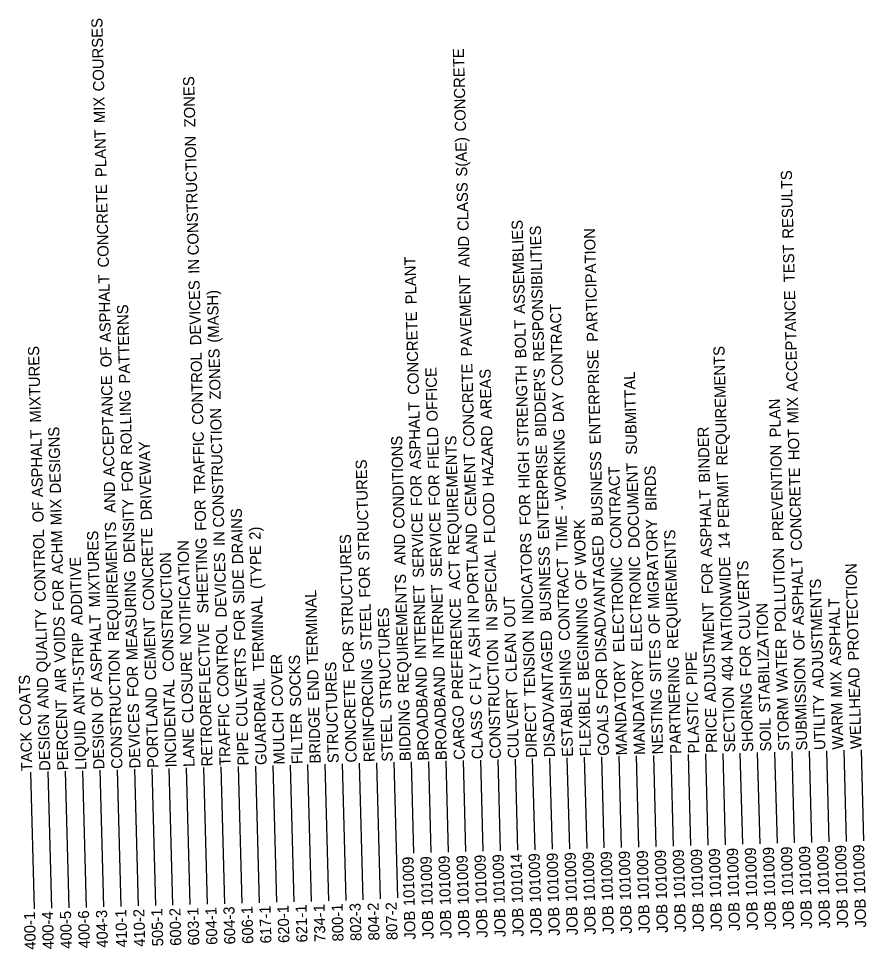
# Model space of a CAD drawing. Extents: x 1930579 to 1931706, y 595585 to 597808.
# Drawn here: x 1931091 to 1931550, y 596431 to 596935 of the extents above; entities that cross this region are included whole.
import ezdxf

# ---------------------------------------------------------------- set-up
doc = ezdxf.new("R2010")
doc.units = 0
doc.layers.add('Default', color=7, linetype='Continuous')

msp = doc.modelspace()

# ---------------------------------------------------------------- linework, layer by layer
at = {"layer": 'Default'}
for p, q in [((1931389.43, 596485.8), (1931388.11, 596535.11)), ((1931398.79, 596486.05), (1931397.46, 596535.36)), ((1931408.14, 596486.3), (1931406.82, 596535.61)), ((1931417.5, 596486.55), (1931416.18, 596535.86)), ((1931426.86, 596486.8), (1931425.53, 596536.11)), ((1931436.21, 596487.06), (1931434.89, 596536.37)), ((1931445.57, 596487.31), (1931444.25, 596536.62)), ((1931454.93, 596487.56), (1931453.6, 596536.87)), ((1931464.28, 596487.81), (1931462.96, 596537.12)), ((1931473.64, 596488.06), (1931472.32, 596537.37)), ((1931483, 596488.31), (1931481.67, 596537.62)), ((1931492.35, 596488.56), (1931491.03, 596537.87)), ((1931501.71, 596488.81), (1931500.39, 596538.12)), ((1931511.07, 596489.07), (1931509.74, 596538.37)), ((1931520.42, 596489.32), (1931519.1, 596538.63)), ((1931529.78, 596489.57), (1931528.46, 596538.88)), ((1931539.14, 596489.82), (1931537.81, 596539.13)), ((1931548.49, 596490.07), (1931547.17, 596539.38)), ((1931202.96, 596456.16), (1931200.97, 596530.09)), ((1931212.32, 596456.42), (1931210.33, 596530.34)), ((1931221.67, 596456.67), (1931219.69, 596530.59)), ((1931231.03, 596456.92), (1931229.04, 596530.84)), ((1931240.39, 596457.17), (1931238.4, 596531.09)), ((1931249.74, 596457.42), (1931247.76, 596531.34)), ((1931259.1, 596457.67), (1931257.11, 596531.59)), ((1931268.46, 596457.92), (1931266.47, 596531.84)), ((1931277.81, 596458.17), (1931275.83, 596532.1)), ((1931287.16, 596458.75), (1931285.18, 596532.35)), ((1931296.51, 596459.37), (1931294.54, 596532.6)), ((1931305.22, 596483.54), (1931303.9, 596532.85)), ((1931314.58, 596483.79), (1931313.25, 596533.1)), ((1931323.93, 596484.04), (1931322.61, 596533.35)), ((1931333.29, 596484.29), (1931331.97, 596533.6)), ((1931342.65, 596484.54), (1931341.32, 596533.85)), ((1931352, 596484.8), (1931350.68, 596534.1)), ((1931361.36, 596485.05), (1931360.04, 596534.36)), ((1931370.72, 596485.3), (1931369.39, 596534.61)), ((1931380.07, 596485.55), (1931378.75, 596534.86)), ((1931100.04, 596453.4), (1931098.05, 596527.32)), ((1931109.39, 596453.65), (1931107.41, 596527.57)), ((1931118.75, 596453.9), (1931116.76, 596527.83)), ((1931128.11, 596454.15), (1931126.12, 596528.08)), ((1931137.46, 596454.41), (1931135.48, 596528.33)), ((1931146.82, 596454.66), (1931144.83, 596528.58)), ((1931156.18, 596454.91), (1931154.19, 596528.83)), ((1931165.53, 596455.16), (1931163.55, 596529.08)), ((1931174.89, 596455.41), (1931172.9, 596529.33)), ((1931184.25, 596455.66), (1931182.26, 596529.58)), ((1931193.6, 596455.91), (1931191.62, 596529.83))]:
    msp.add_line(p, q, dxfattribs=at)

# ---------------------------------------------------------------- texts
for s, p in [(' COURSES', (1931137.81, 596893.29)), (' CONCRETE', (1931333.46, 596871.55)), (' ZONES', (1931187.1, 596873.81)), (' MIX', (1931138.27, 596876.12)), (' PLANT', (1931139.05, 596846.95)), (' CONSTRUCTION', (1931188.96, 596804.65)), (' S(AE)', (1931334.12, 596847.17)), (' RESULTS', (1931510.58, 596813.62)), (' CONCRETE', (1931140.37, 596798.04)), (' CLASS', (1931334.91, 596817.8)), (' ASSEMBLIES', (1931365.37, 596772.94)), (' RESPONSIBILITIES', (1931375.82, 596747.14)), (' AND', (1931335.43, 596798.23)), (' PARTICIPATION', (1931404.79, 596757.85)), (' TEST', (1931511.22, 596790.04)), (' IN', (1931189.23, 596794.63)), (' PLANT', (1931306.71, 596778.13)), (' ASPHALT', (1931141.45, 596757.68)), (' DEVICES', (1931190.26, 596755.95)), (' PAVEMENT', (1931336.73, 596749.96)), (' (MASH)', (1931199.98, 596757.37)), (' ACCEPTANCE', (1931512.8, 596730.87)), (' PATTERNS', (1931151.81, 596735.29)), (' CONTRACT', (1931385.93, 596733.89)), (' CONCRETE', (1931308.02, 596729.22)), (' BOLT', (1931366.02, 596748.89)), (' MIXTURES', (1931103.6, 596714.16)), (' OF', (1931141.82, 596744.1)), (' REQUIREMENTS', (1931474.86, 596690.96)), (' CONTROL', (1931191.42, 596712.94)), (' ZONES', (1931200.81, 596726.61)), (' ENTERPRISE', (1931406.28, 596702.41)), (' CONCRETE', (1931338.04, 596701.05)), (' STRENGTH', (1931367.3, 596701.14)), (' ACCEPTANCE', (1931143.4, 596684.94)), (' OFFICE', (1931318.17, 596714.75)), (' AREAS', (1931347.39, 596715.99)), (" BIDDER'S", (1931376.91, 596706.39)), (' SUBMITTAL', (1931425.94, 596696.79)), (' ROLLING', (1931152.84, 596696.7)), (' DAY', (1931386.45, 596714.4)), (' ASPHALT', (1931309.11, 596688.86)), (' PLAN', (1931503.71, 596706.18)), (' MIX', (1931513.26, 596713.7)), (' CONSTRUCTION', (1931202.66, 596657.45)), (' ASPHALT', (1931104.69, 596673.81)), (' DESIGNS', (1931114.39, 596675.82)), (' TRAFFIC', (1931192.42, 596675.57)), (' FIELD', (1931318.85, 596689.13)), (' HAZARD', (1931348.37, 596679.65)), (' WORKING', (1931387.6, 596671.62)), (' BINDER', (1931465.36, 596681.69)), (' HOT', (1931513.8, 596693.85)), (' CONDITIONS', (1931300.22, 596656.69)), (' REQUIREMENTS', (1931329.86, 596642.54)), (' DRIVEWAY', (1931163.55, 596661.3)), (' ENTERPRISE', (1931378.4, 596650.96)), (' PREVENTION', (1931505.22, 596650.05)), (' CEMENT', (1931339.05, 596663.5)), (' HIGH', (1931367.91, 596678.54)), (' BUSINESS', (1931407.47, 596658.14)), (' FOR', (1931153.38, 596676.8)), (' STRUCTURES', (1931281.17, 596639.42)), (' CONTRACT', (1931417.55, 596645.95)), (' DOCUMENT', (1931427.29, 596646.21)), (' BIRDS', (1931436.51, 596666.41)), (' CONCRETE', (1931515.11, 596644.94)), (' FOR', (1931309.64, 596668.96)), (' FOR', (1931319.39, 596669.22)), (' PERMIT', (1931475.77, 596657.14)), (' AND', (1931143.93, 596665.36)), (' FLOOD', (1931349.19, 596648.9)), (' FOR', (1931368.44, 596658.64)), (' ASPHALT', (1931466.44, 596641.33)), (' OF', (1931105.05, 596660.23)), (' MIX', (1931114.85, 596658.65)), (' DENSITY', (1931154.41, 596638.21)), (' FOR', (1931192.96, 596655.66)), (' -', (1931387.73, 596666.77)), (' DRAINS', (1931212.95, 596637.55)), (' SERVICE', (1931310.68, 596630.28)), (' SERVICE', (1931320.43, 596630.55)), (' REQUIREMENTS', (1931145.79, 596595.95)), (' PORTLAND', (1931340.32, 596615.99)), (' TIME', (1931388.32, 596644.87)), (' WORK', (1931398.28, 596637.02)), (' MIGRATORY', (1931437.93, 596613.39)), (' CONTROL', (1931106.21, 596617.22)), (' ACHM', (1931115.56, 596632.28)), (' MIXTURES', (1931135.55, 596614.25)), (' CONCRETE', (1931164.86, 596612.38)), (' IN', (1931202.93, 596647.43)), (' 2)', (1931222.35, 596650.78)), (' INDICATORS', (1931369.88, 596605.07)), (' REQUIREMENTS', (1931448.27, 596591.66)), (' 14', (1931476.07, 596645.9)), (' NOTIFICATION', (1931184.86, 596594.01)), (' SHEETING', (1931194.16, 596611.02)), (' STRUCTURES', (1931272.51, 596599.02)), (' AND', (1931300.74, 596637.12)), (' DISADVANTAGED', (1931409.44, 596584.53)), (' DEVICES', (1931203.97, 596608.75)), (' (TYPE', (1931223.06, 596624.22)), (' SPECIAL', (1931350.2, 596611.47)), (' BUSINESS', (1931379.59, 596606.68)), (' POLLUTION', (1931506.54, 596600.92)), (' ADDITIVE', (1931126.05, 596604.61)), (' CONSTRUCTION', (1931175.5, 596579.44)), (' ACT', (1931330.37, 596623.62)), (' CONTRACT', (1931389.62, 596596.15)), (' ELECTRONIC', (1931419.05, 596589.94)), (' ELECTRONIC', (1931428.8, 596590.2)), (' NATIONWIDE', (1931477.56, 596590.48)), (' CULVERTS', (1931487.14, 596596.78)), (' ASPHALT', (1931516.19, 596604.59)), (' MEASURING', (1931155.82, 596585.65)), (' SIDE', (1931213.53, 596616.11)), (' FOR', (1931281.71, 596619.51)), (' OF', (1931398.65, 596623.44)), (' FOR', (1931466.97, 596621.43)), (' PROTECTION', (1931545.97, 596585.51)), (' FOR', (1931116.09, 596612.37)), (' REQUIREMENTS', (1931302.61, 596567.71)), (' ADJUSTMENTS', (1931526.86, 596570.46)), (' TERMINAL', (1931253.42, 596583.26)), (' INTERNET', (1931311.86, 596586.22)), (' INTERNET', (1931321.61, 596586.48)), (' TERMINAL', (1931224.25, 596579.82)), (' PREFERENCE', (1931331.95, 596564.46)), (' OUT', (1931360.17, 596603.42)), (' BEGINNING', (1931399.96, 596574.61)), (' ASPHALT', (1931536.29, 596582.66)), (' STEEL', (1931282.48, 596590.93)), (' STRUCTURES', (1931293.08, 596559.3)), (' ADJUSTMENT', (1931468.54, 596562.93)), (' STABILIZATION', (1931497.96, 596557.34)), (' QUALITY', (1931107.23, 596579.1)), (' VOIDS', (1931116.84, 596584.41)), (' ASPHALT', (1931136.63, 596573.89)), (' CEMENT', (1931165.87, 596574.84)), (' FOR', (1931214.06, 596596.21)), (' IN', (1931340.59, 596605.97)), (' IN', (1931350.47, 596601.45)), (' OF', (1931438.29, 596599.81)), ('RETROREFLECTIVE', (1931196.32, 596530.43)), (' CONTROL', (1931205.12, 596565.75)), (' ANTI-STRIP', (1931127.36, 596556.09)), (' ASH', (1931341.1, 596587.08)), (' CLEAN', (1931360.96, 596573.83)), (' TENSION', (1931370.92, 596566.17)), ('DISADVANTAGED', (1931381.5, 596535.41)), (' OF', (1931516.56, 596591.01)), (' FOR', (1931273.04, 596579.11)), ('CONSTRUCTION', (1931352.26, 596534.62)), (' SITES', (1931438.99, 596573.7)), (' FOR', (1931487.68, 596576.87)), (' WATER', (1931507.41, 596568.44)), ('CONSTRUCTION', (1931147.59, 596529.13)), (' CLOSURE', (1931186, 596551.62)), (' CULVERTS', (1931215.31, 596549.61)), (' COVER', (1931234.52, 596560.6)), ('ESTABLISHING', (1931391.25, 596535.67)), (' PIPE', (1931458.55, 596572.1)), (' SOCKS', (1931244.28, 596560.5)), ('STRUCTURES', (1931264.54, 596532.27)), ('REINFORCING', (1931284.04, 596532.79)), (' FLY', (1931341.57, 596569.45)), ('MANDATORY', (1931420.49, 596536.45)), ('MANDATORY', (1931430.23, 596536.71)), ('PARTNERING', (1931449.73, 596537.24)), (' 404', (1931477.99, 596574.59)), ('SUBMISSION', (1931517.95, 596539.07)), (' AIR', (1931117.28, 596568.22)), (' FOR', (1931156.36, 596565.74)), (' END', (1931253.95, 596563.69)), ('BROADBAND', (1931313.28, 596533.57)), ('BROADBAND', (1931323.02, 596533.84)), (' FOR', (1931409.98, 596564.63)), (' MIX', (1931536.75, 596565.49)), ('WELLHEAD', (1931547.19, 596539.85)), (' COATS', (1931098.25, 596550.15)), (' AND', (1931107.76, 596559.53)), ('INCIDENTAL', (1931176.83, 596529.91)), ('GUARDRAIL', (1931225.56, 596531.22)), ('CONCRETE', (1931274.29, 596532.53)), (' OF', (1931137, 596560.31)), ('PORTLAND', (1931167.08, 596529.65)), ('CULVERT', (1931362.01, 596534.88)), ('FLEXIBLE', (1931400.99, 596535.93)), ('NESTING', (1931439.98, 596536.97)), ('PLASTIC', (1931459.47, 596537.5)), ('SECTION', (1931478.97, 596538.02)), ('SHORING', (1931488.71, 596538.28)), ('PERCENT', (1931118.35, 596528.34)), ('BIDDING', (1931303.53, 596533.31)), (' C', (1931341.79, 596561.4)), ('STORM', (1931508.21, 596538.81)), ('UTILITY', (1931527.7, 596539.33)), ('DEVICES', (1931157.33, 596529.39)), ('TRAFFIC', (1931206.07, 596530.7)), ('BRIDGE', (1931254.8, 596532)), ('CARGO', (1931332.77, 596534.1)), ('CLASS', (1931342.52, 596534.36)), ('DIRECT', (1931371.76, 596535.14)), ('GOALS', (1931410.74, 596536.19)), ('PRICE', (1931469.22, 596537.76)), ('WARM', (1931537.45, 596539.59)), ('DESIGN', (1931108.6, 596528.08)), ('DESIGN', (1931137.84, 596528.86)), ('MULCH', (1931235.3, 596531.48)), ('FILTER', (1931245.05, 596531.74)), ('STEEL', (1931293.78, 596533.05)), ('SOIL', (1931498.46, 596538.54)), ('LIQUID', (1931128.09, 596528.6)), ('LANE', (1931186.57, 596530.17)), ('TACK', (1931098.85, 596527.82)), ('PIPE', (1931215.81, 596530.96)), (' 101009', (1931442.15, 596456.34)), (' 101009', (1931451.89, 596456.6)), (' 101009', (1931461.64, 596456.86)), (' 101009', (1931471.38, 596457.12)), (' 101009', (1931481.13, 596457.39)), (' 101009', (1931490.88, 596457.65)), (' 101009', (1931500.62, 596457.91)), (' 101009', (1931510.37, 596458.17)), (' 101009', (1931520.12, 596458.43)), (' 101009', (1931529.86, 596458.69)), (' 101009', (1931539.61, 596458.96)), (' 101009', (1931549.36, 596459.22)), (' 101009', (1931305.69, 596452.68)), (' 101009', (1931315.44, 596452.94)), (' 101009', (1931325.19, 596453.2)), (' 101009', (1931334.93, 596453.46)), (' 101009', (1931344.68, 596453.72)), (' 101009', (1931354.43, 596453.98)), (' 101014', (1931364.17, 596454.25)), (' 101009', (1931373.92, 596454.51)), (' 101009', (1931383.67, 596454.77)), (' 101009', (1931393.41, 596455.03)), (' 101009', (1931403.16, 596455.29)), (' 101009', (1931412.91, 596455.55)), (' 101009', (1931422.65, 596455.82)), (' 101009', (1931432.4, 596456.08)), ('606-1', (1931218.4, 596434.47)), ('617-1', (1931228.15, 596434.73)), ('620-1', (1931237.89, 596434.99)), ('621-1', (1931247.64, 596435.25)), ('734-1', (1931257.39, 596435.51)), ('800-1', (1931267.13, 596435.78)), ('802-3', (1931276.88, 596436.04)), ('804-2', (1931286.63, 596436.3)), ('807-2', (1931296.37, 596436.56)), ('JOB', (1931403.59, 596439.44)), ('JOB', (1931413.33, 596439.7)), ('JOB', (1931423.08, 596439.96)), ('JOB', (1931432.82, 596440.22)), ('JOB', (1931442.57, 596440.48)), ('JOB', (1931452.32, 596440.75)), ('JOB', (1931462.06, 596441.01)), ('JOB', (1931471.81, 596441.27)), ('JOB', (1931481.56, 596441.53)), ('JOB', (1931491.3, 596441.79)), ('JOB', (1931501.05, 596442.05)), ('JOB', (1931510.8, 596442.32)), ('JOB', (1931520.54, 596442.58)), ('JOB', (1931530.29, 596442.84)), ('JOB', (1931540.04, 596443.1)), ('JOB', (1931549.78, 596443.36)), ('400-1', (1931100.77, 596431.31)), ('400-4', (1931110.52, 596431.57)), ('400-5', (1931120.26, 596431.83)), ('400-6', (1931130.01, 596432.09)), ('404-3', (1931139.76, 596432.36)), ('410-1', (1931150.18, 596432.64)), ('410-2', (1931159.92, 596432.9)), ('505-1', (1931169.67, 596433.16)), ('600-2', (1931179.42, 596433.42)), ('603-1', (1931189.16, 596433.68)), ('604-1', (1931198.91, 596433.94)), ('604-3', (1931208.66, 596434.21)), ('JOB', (1931306.12, 596436.82)), ('JOB', (1931315.87, 596437.08)), ('JOB', (1931325.61, 596437.35)), ('JOB', (1931335.36, 596437.61)), ('JOB', (1931345.11, 596437.87)), ('JOB', (1931354.85, 596438.13)), ('JOB', (1931364.6, 596438.39)), ('JOB', (1931374.35, 596438.65)), ('JOB', (1931384.09, 596438.91)), ('JOB', (1931393.84, 596439.18))]:
    msp.add_text(s, height=6, rotation=91.5377, dxfattribs=at).set_placement(p)

doc.saveas('drawing.dxf')
